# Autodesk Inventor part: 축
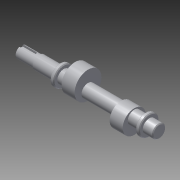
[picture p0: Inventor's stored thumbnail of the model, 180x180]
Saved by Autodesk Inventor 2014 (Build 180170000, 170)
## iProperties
Created: 2014-12
Part Number: 축
Material: 알루미늄 6061
Document SubType Name: Modeling
Designer: Owner
Density: 2.71 g/cm^3
Appearance: 알루미늄 - 평지
Mass: 170.354 g
Surface Area: 153.402 cm^2
Volume: 62.8614 cm^3
Author: Owner
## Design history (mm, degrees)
sketch "스케치1"
  geometry: L1 (-90, 0)-(90, 0); L2 (-90, 0)-(-90, 7.5); L3 (-90, 7.5)-(-66, 7.5); L4 (-66, 7.5)-(-66, 8.5); L5 (-66, 8.5)-(-39, 8.5); L6 (-39, 8.5)-(-39, 13); L7 (-39, 13)-(-34, 13); L8 (-34, 13)-(-34, 8.5); L9 (-34, 8.5)-(72, 8.5); L10 (72, 8.5)-(72, 13); L11 (72, 13)-(77, 13); L12 (77, 13)-(77, 8.5); L13 (77, 8.5)-(90, 8.5); L14 (90, 8.5)-(90, 0); 2 further points
  constraints: 28 end point, 7 parallel, 4 perpendicular, 3 collinear, 3 horizontal alignment, 1 coincident, 1 horizontal, 1 midpoint
  dimensions: "d0" = 180 distance of L1.start L1.end; "d2" = 15 diameter of L3 L1; "d3" = 17 diameter of L5 L1; "d4" = 26 diameter of L7 L1; "d5" = 5 distance of L10.end L11.end; "d6" = 13 distance of L12.end L13.end; "d7" = 24 distance of L2.end L3.end; "d8" = 27 distance of L4.end L5.end
revolve "회전1" sketch "스케치1" stored, may be unused: angle "d9" = 90 deg
node "작업 평면1"
sketch "스케치2"
  geometry: L1 (-7.547, 0)-(5.5, 0); L2 (-12, -2.5)-(5.5, -2.5); L3 (5.5, 2.5)-(-12, 2.5); L4 (-12, 2.5)-(-12, -2.5); L5 (-12, -7.5)-(-12, 7.5) reference; A1 r 2.5 centre (5.5, 0) between (5.5, -2.5) and (5.5, 2.5); 4 further points
  constraints: 10 end point, 4 midpoint, 2 horizontal alignment, 2 point on circle, 2 tangent, 1 centre point, 1 horizontal, 1 parallel, 1 perpendicular, 1 vertical
  dimensions: "d10" = 20 dimension on A1 L5; "d11" = 5 distance of L3.end L2.start
extrude "돌출1" cut sketch "스케치2" distance "d12" = 3; taper "d13" = 0 deg
node "작업 평면3"
  node "작업 평면2"
sketch "스케치3"
  geometry: C1 r 17.5 at (0, 6); 1 further point
  constraints: 1 centre point, 1 vertical alignment
  dimensions: "d16" = 35 diameter of C1; "d17" = 6 distance of point (0, 0) C1.centre
extrude "돌출2" join sketch "스케치3" distance "d18" = 17; taper "d19" = 0 deg
node "작업 평면4"
sketch "스케치4"
  geometry: C1 r 15 at (0, -5); 1 further point
  constraints: 1 centre point, 1 vertical alignment
  dimensions: "d22" = 30 diameter of C1; "d23" = 5 distance of C1.centre point (0, 0)
extrude "돌출3" join sketch "스케치4" distance "d24" = 17; taper "d25" = 0 deg
chamfer "모따기1" distance "d26" = 1; stored, may be unused: second distance "d27" = 2, angle "d28" = 45 deg
node "솔리드1"
other parameters: "d15" = 70.5
